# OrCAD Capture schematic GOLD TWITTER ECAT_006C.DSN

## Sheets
1 PAGE1_PROPRIETARY: title: PROPRIETARY; rev: C; note: GOLD TWITTER ECAT
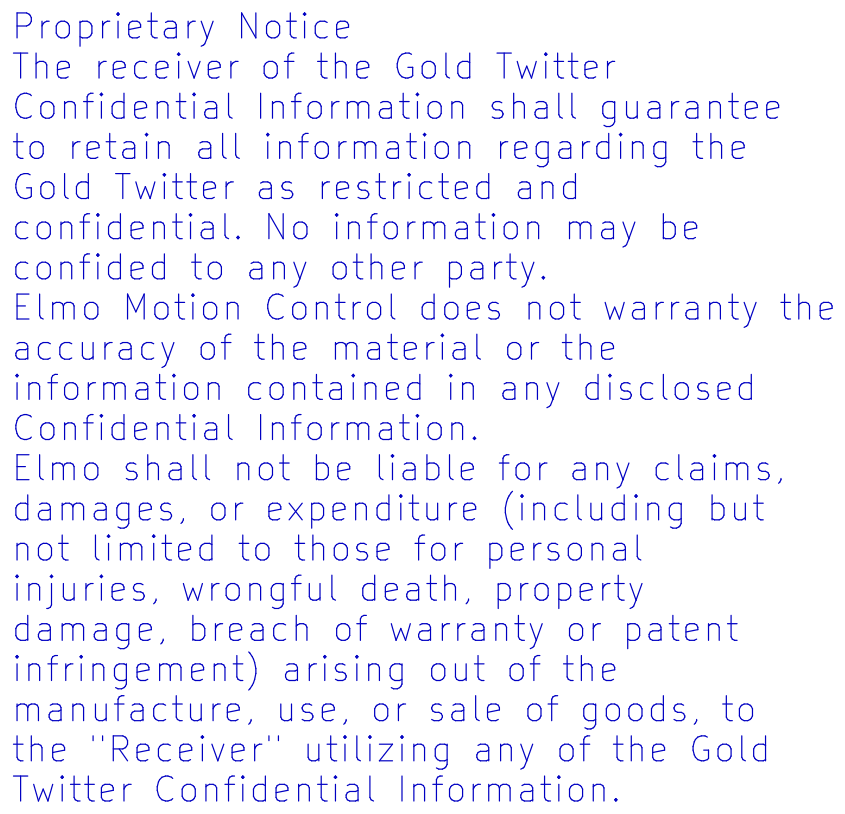
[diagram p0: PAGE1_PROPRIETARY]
2 PAGE3: size A3; title: TWI_E_B_ETH_Connectors 02_200v; note: GOLD TWITTER ECAT_006C.DSN
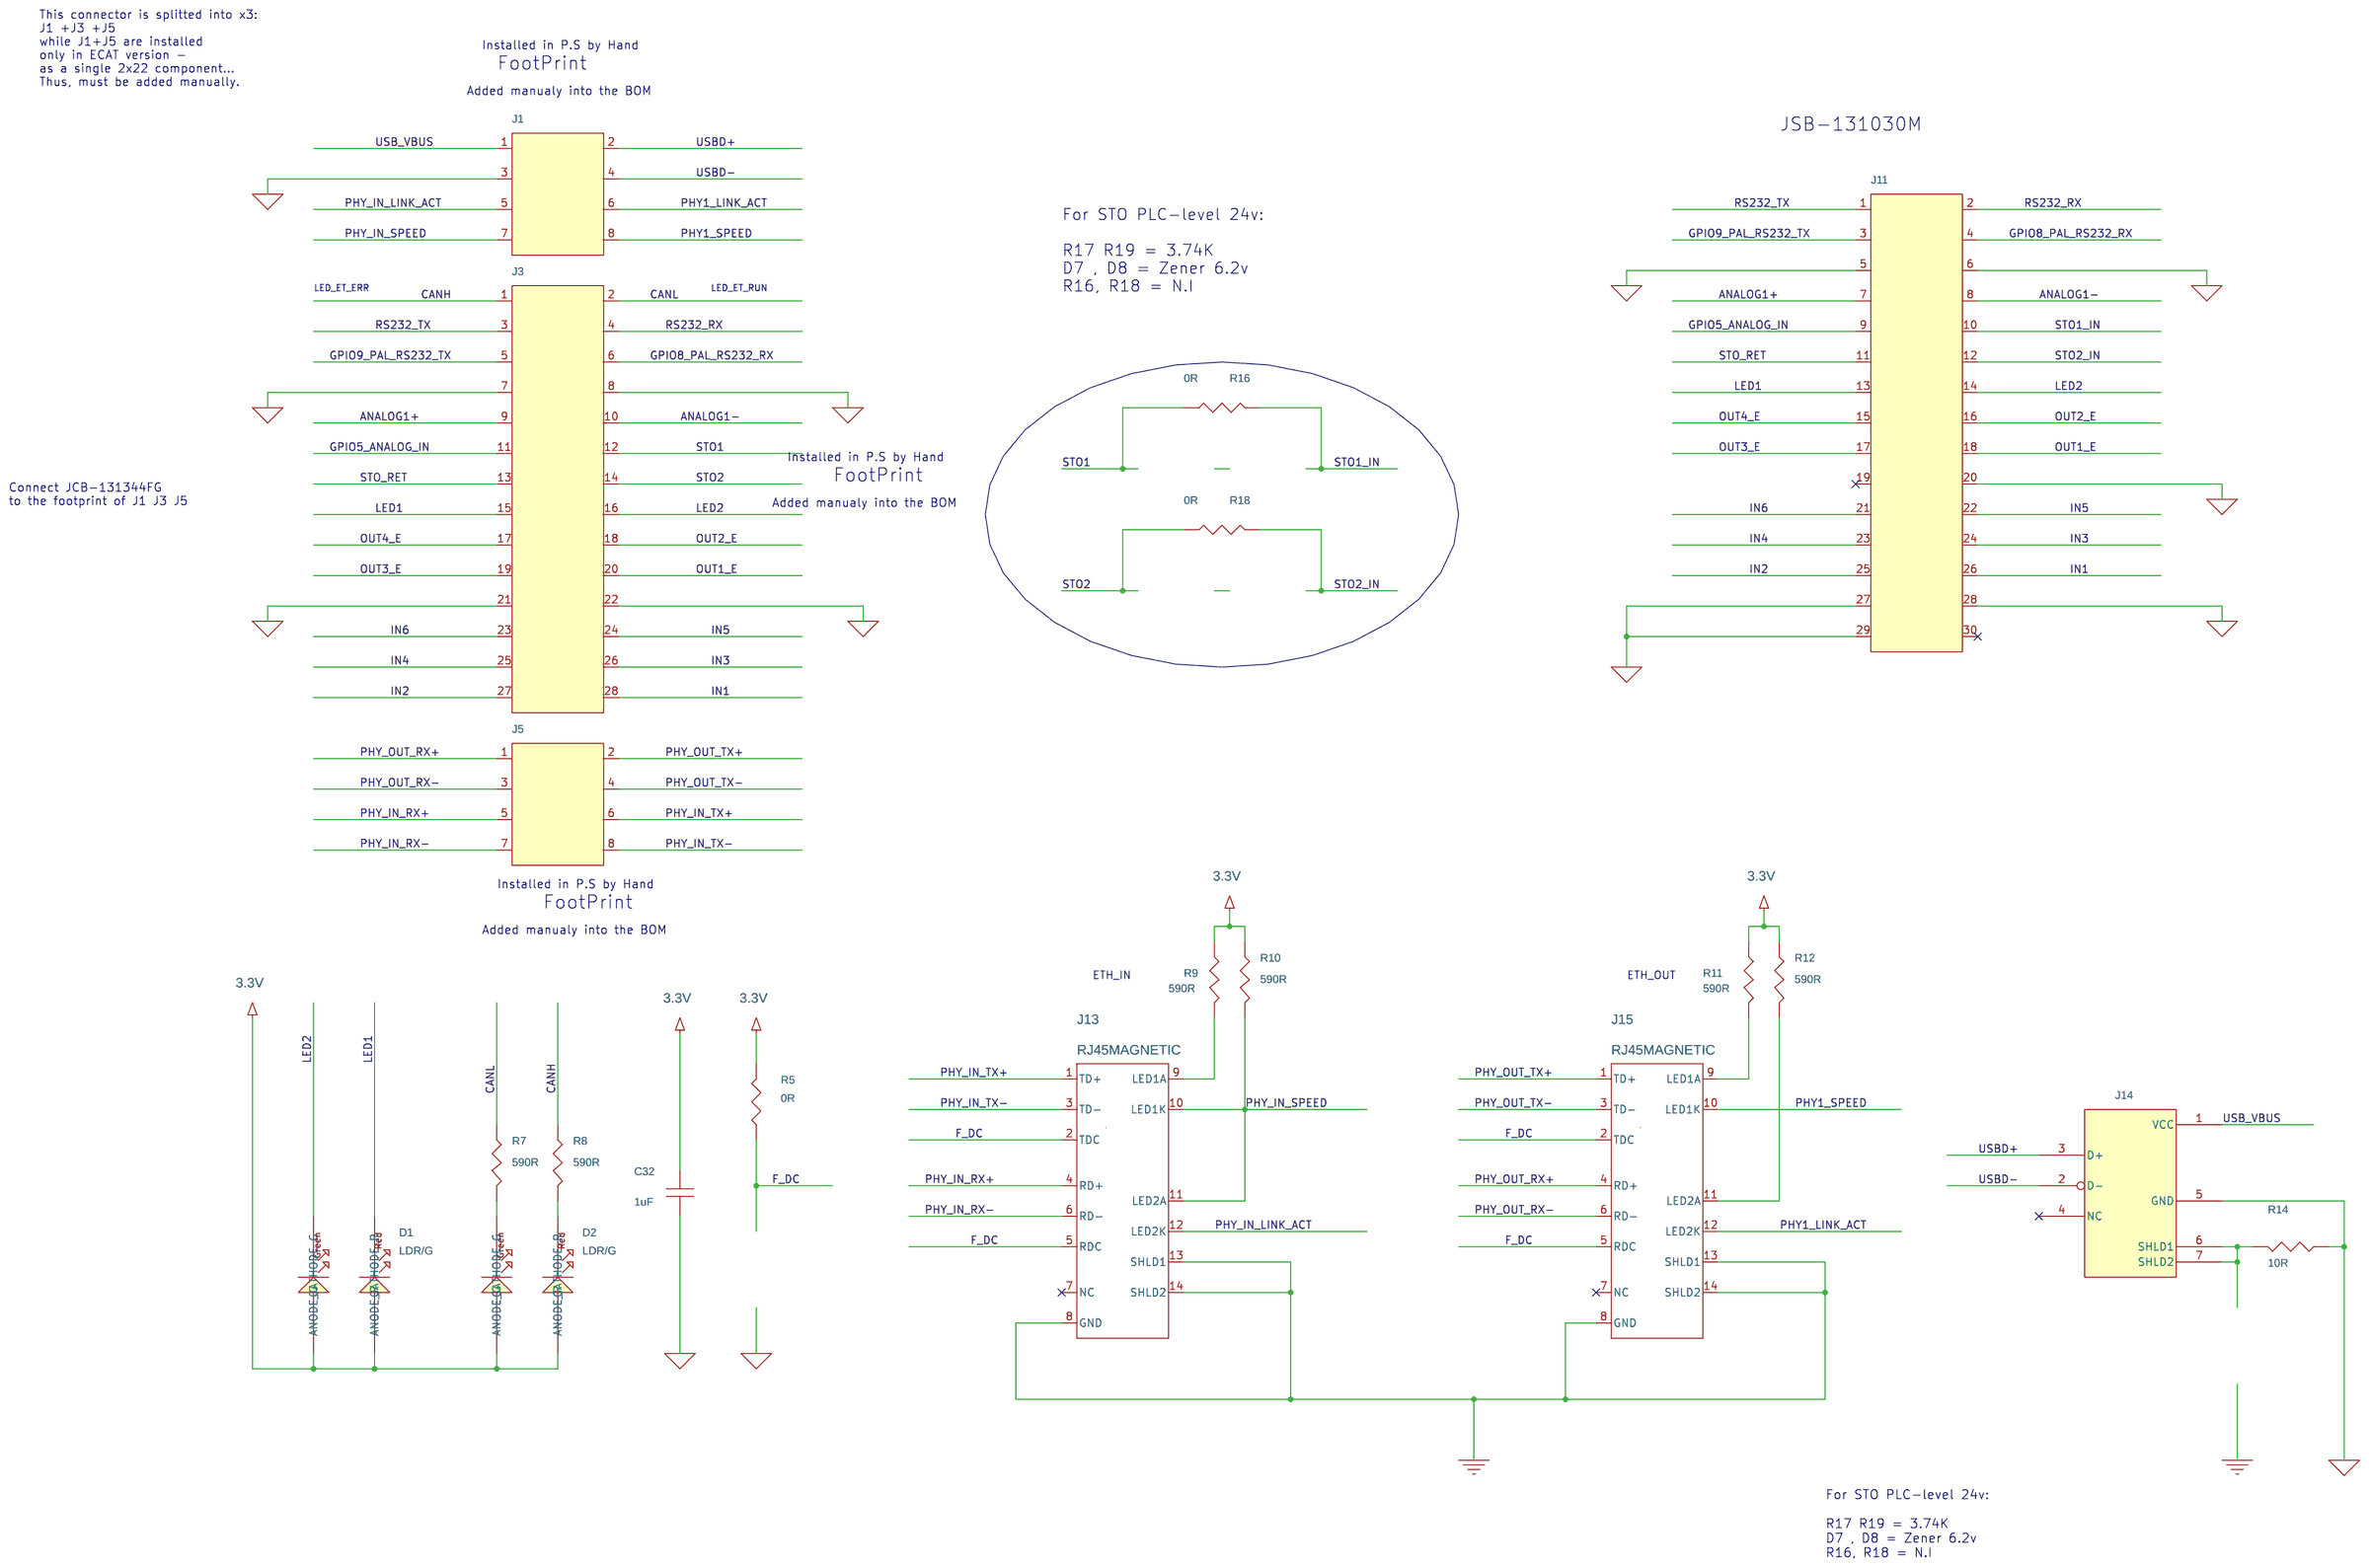
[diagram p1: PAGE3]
3 PAGE2: size A4; title: TWI_E_B_ETH_Connectors 01_200v; note: GOLD TWITTER ECAT_006C.DSN
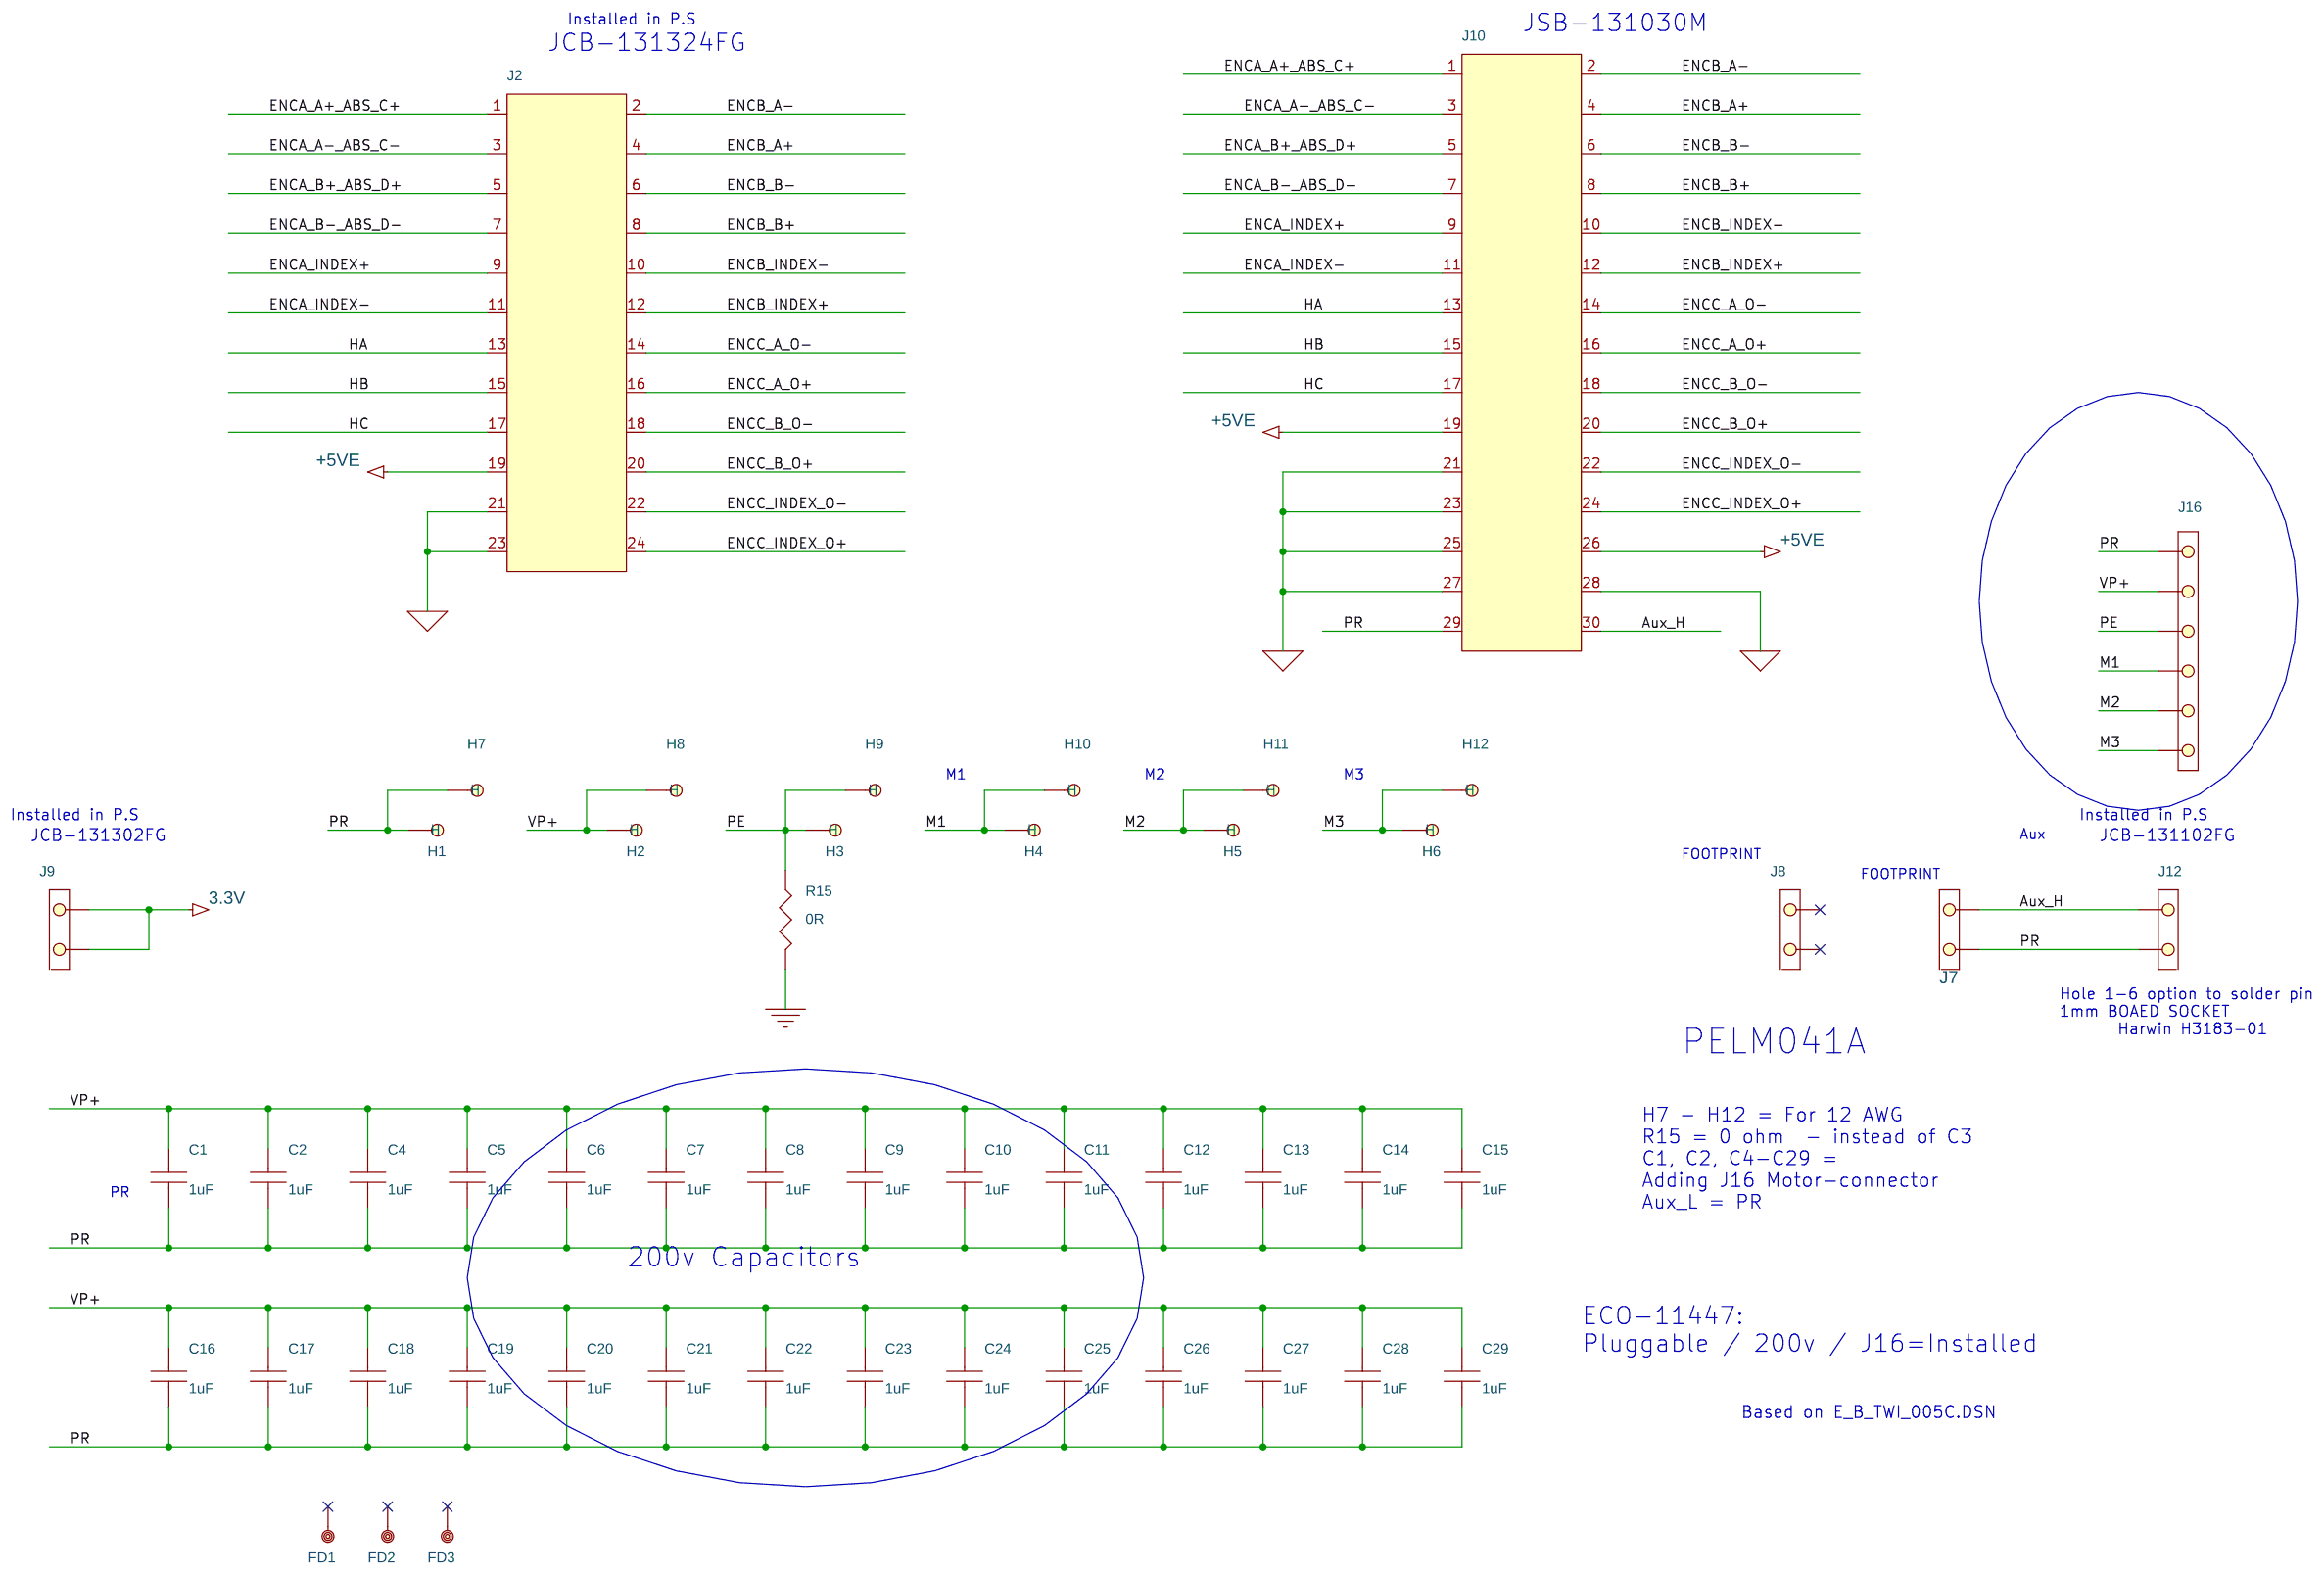
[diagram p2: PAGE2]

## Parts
sheet PAGE2
C1  1uF
C2  1uF
C4  1uF
C5  1uF
C6  1uF
C7  1uF
C8  1uF
C9  1uF
C10  1uF
C11  1uF
C12  1uF
C13  1uF
C14  1uF
C15  1uF
C16  1uF
C17  1uF
C18  1uF
C19  1uF
C20  1uF
C21  1uF
C22  1uF
C23  1uF
C24  1uF
C25  1uF
C26  1uF
C27  1uF
C28  1uF
C29  1uF
FD1  FD1
FD2  FD1
FD3  FD1
H1  H8
H2  H8
H3  H8
H4  H8
H5  H8
H6  H8
H7  H52
H8  H52
H9  H52
H10  H52
H11  H52
H12  H52
J2  J
J7  J
J8  J
J9  J
J10  J
J12  J
J16  J
R15  0R
sheet PAGE3
C32  1uF
D1  LDR/G
D2  LDR/G
J1  J
J3  J
J5  J
J11  J
J13  RJ45MAGNETIC
J14  USB
J15  RJ45MAGNETIC
R5  0R
R7  590R
R8  590R
R9  590R
R10  590R
R11  590R
R12  590R
R14  10R
R16  0R
R18  0R

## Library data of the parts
C1 C2 C4-C29 = C1uF_200v_X7R_1206
FD1-FD3 = FIDUCIAL1_FD1
H1-H6 = HOLE08_H08
H7-H12 = HOLE52_H52
J2 = HEADER2x12PF1.27_4.3_HEADER194
J7 = HEADER52A_FP12
J8 = HEADER2P1.27mmHEADER278A
J9 = HEADER2PF1.27mm_4.3_HEADER278
J10 J11 = HEADER2x15P1mm_HEADER283
J12 = HEADER2PF2mm_4.3mm_HEADER52
J16 = TB6P3.5mm_TB54
R15 = 0R_1206
C32 = C1uF_10v_X5R_0402
D1 D2 = LED_BICOLOR_LED06
J1 J5 = HEADER2x4P1.27mm_HEADER271A
J3 = HEADER2x14P1_0.27_HEADER245B
J13 J15 = CON8P_RJ45MAGNET_Straight_CON37
J14 = USBType-B_TH_STR_5Pins_CON40
R5 R16 R18 = 0R_0402
R7-R12 = 590R1%_0402
R14 = 10R1%_0402

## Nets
3.3V: C32.1 D1.1(ANODE_R) D1.3(ANODE_G) D2.1(ANODE_R) D2.3(ANODE_G) J9.1 J9.2 R5.2 R9.1 R10.1 R11.1 R12.1
+5VE: J2.19 J10.19 J10.26
GND: C32.2 J1.3 J2.21 J2.23 J3.7 J3.8 J3.21 J3.22 J10.21 J10.23 J10.25 J10.27 J10.28 J11.5 J11.6 J11.20 J11.27 J11.28 J11.29 J14.5(GND) R14.1
GND_POWER: J13.8(GND) J13.13(SHLD1) J13.14(SHLD2) J15.8(GND) J15.13(SHLD1) J15.14(SHLD2) R15.2
ANALOG1+: J3.9 J11.7
ANALOG1-: J3.10 J11.8
Aux_H: J7.1 J10.30 J12.1
CANH: J3.1 R8.1
CANL: J3.2 R7.1
ENCA_A+_ABS_C+: J2.1 J10.1
ENCA_A-_ABS_C-: J2.3 J10.3
ENCA_B+_ABS_D+: J2.5 J10.5
ENCA_B-_ABS_D-: J2.7 J10.7
ENCA_INDEX+: J2.9 J10.9
ENCA_INDEX-: J2.11 J10.11
ENCB_A+: J2.4 J10.4
ENCB_A-: J2.2 J10.2
ENCB_B+: J2.8 J10.8
ENCB_B-: J2.6 J10.6
ENCB_INDEX+: J2.12 J10.12
ENCB_INDEX-: J2.10 J10.10
ENCC_A_O+: J2.16 J10.16
ENCC_A_O-: J2.14 J10.14
ENCC_B_O+: J2.20 J10.20
ENCC_B_O-: J2.18 J10.18
ENCC_INDEX_O+: J2.24 J10.24
ENCC_INDEX_O-: J2.22 J10.22
F_DC: J13.2(TDC) J13.5(RDC) J15.2(TDC) J15.5(RDC) R5.1
GPIO5_ANALOG_IN: J3.11 J11.9
GPIO8_PAL_RS232_RX: J3.6 J11.4
GPIO9_PAL_RS232_TX: J3.5 J11.3
HA: J2.13 J10.13
HB: J2.15 J10.15
HC: J2.17 J10.17
IN1: J3.28 J11.26
IN2: J3.27 J11.25
IN3: J3.26 J11.24
IN4: J3.25 J11.23
IN5: J3.24 J11.22
IN6: J3.23 J11.21
LED1: D1.2(CATHODE_R) J3.15 J11.13
LED2: D1.4(CATHODE_G) J3.16 J11.14
M1: H4.1(H) H10.1(H) J16.4
M2: H5.1(H) H11.1(H) J16.5
M3: H6.1(H) H12.1(H) J16.6
OUT1_E: J3.20 J11.18
OUT2_E: J3.18 J11.16
OUT3_E: J3.19 J11.17
OUT4_E: J3.17 J11.15
PE: H3.1(H) H9.1(H) J16.3 R15.1
PHY1_LINK_ACT: J1.6 J15.12(LED2K)
PHY1_SPEED: J1.8 J15.10(LED1K)
PHY_IN_LINK_ACT: J1.5 J13.12(LED2K)
PHY_IN_RX+: J5.5 J13.4(RD+)
PHY_IN_RX-: J5.7 J13.6(RD-)
PHY_IN_SPEED: J1.7 J13.10(LED1K)
PHY_IN_TX+: J5.6 J13.1(TD+)
PHY_IN_TX-: J5.8 J13.3(TD-)
PHY_OUT_RX+: J5.1 J15.4(RD+)
PHY_OUT_RX-: J5.3 J15.6(RD-)
PHY_OUT_TX+: J5.2 J15.1(TD+)
PHY_OUT_TX-: J5.4 J15.3(TD-)
PR: C1.2 C2.2 C4.2 C5.2 C6.2 C7.2 C8.2 C9.2 C10.2 C11.2 C12.2 C13.2 C14.2 C15.2 C16.2 C17.2 C18.2 C19.2 C20.2 C21.2 C22.2 C23.2 C24.2 C25.2 C26.2 C27.2 C28.2 C29.2 H1.1(H) H7.1(H) J7.2 J10.29 J12.2 J16.1
RS232_RX: J3.4 J11.2
RS232_TX: J3.3 J11.1
STO1: J3.12 R16.1
STO1_IN: J11.10 R16.2
STO2: J3.14 R18.1
STO2_IN: J11.12 R18.2
STO_RET: J3.13 J11.11
USB_VBUS: J1.1 J14.1(VCC)
USBD+: J1.2 J14.3(D+)
USBD-: J1.4 J14.2(D-)
VP+: C1.1 C2.1 C4.1 C5.1 C6.1 C7.1 C8.1 C9.1 C10.1 C11.1 C12.1 C13.1 C14.1 C15.1 C16.1 C17.1 C18.1 C19.1 C20.1 C21.1 C22.1 C23.1 C24.1 C25.1 C26.1 C27.1 C28.1 C29.1 H2.1(H) H8.1(H) J16.2
N14935954: D2.4(CATHODE_G) R7.2
N14935988: D2.2(CATHODE_R) R8.2
N16763388: J13.9(LED1A) R9.2
N16763395: J13.11(LED2A) R10.2
N16763402: J15.9(LED1A) R11.2
N16763409: J15.11(LED2A) R12.2
N16765941: J14.6(SHLD1) J14.7(SHLD2) R14.2

Not connected (* = marked no-connect by the designer): FD1 1*; FD2 1*; FD3 1*; J8 1* 2*; J11 19* 30*; J13 7(NC)*; J14 4(NC)*; J15 7(NC)*

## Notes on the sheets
sheet 1
- Proprietary Notice
  The receiver of the Gold Twitter
  Confidential Information shall guarantee
  to retain all information regarding the
  Gold Twitter as restricted and
  confidential. No information may be
  confided to any other party.
  Elmo Motion Control does not warranty the
  accuracy of the material or the
  information contained in any disclosed
  Confidential Information.
  Elmo shall not be liable for any claims,
  damages, or expenditure (including but
  not limited to those for personal
  injuries, wrongful death, property
  damage, breach of warranty or patent
  infringement) arising out of the
  manufacture, use, or sale of goods, to
  the "Receiver" utilizing any of the Gold
  Twitter Confidential Information.
sheet 2
- This connector is splitted into x3:
  J1 +J3 +J5
  while J1+J5 are installed
  only in ECAT version -
  as a single 2x22 component...
  Thus, must be added manually.
- Installed in P.S by Hand
- FootPrint
- Added manualy into the BOM
- JSB-131030M
- For STO PLC-level 24v:
  R17 R19 = 3.74K
  D7 , D8 = Zener 6.2v
  R16, R18 = N.I
- LED_ET_ERR
- LED_ET_RUN
- Installed in P.S by Hand
- FootPrint
- Connect JCB-131344FG
  to the footprint of J1 J3 J5
- Added manualy into the BOM
- Installed in P.S by Hand
- FootPrint
- Added manualy into the BOM
- ETH_IN
- ETH_OUT
- For STO PLC-level 24v:
  R17 R19 = 3.74K
  D7 , D8 = Zener 6.2v
  R16, R18 = N.I
sheet 3
- Installed in P.S
- JSB-131030M
- JCB-131324FG
- M1
- M2
- M3
- Installed in P.S
- Installed in P.S
- JCB-131302FG
- Aux
- JCB-131102FG
- FOOTPRINT
- FOOTPRINT
- Hole 1-6 option to solder pin
  1mm BOAED SOCKET
         Harwin H3183-01
- PELM041A
- H7 - H12 = For 12 AWG
  R15 = 0 ohm  - instead of C3
  C1, C2, C4-C29 =
  Adding J16 Motor-connector
  Aux_L = PR
- PR
- 200v Capacitors
- ECO-11447:
  Pluggable / 200v / J16=Installed
- Based on E_B_TWI_005C.DSN
